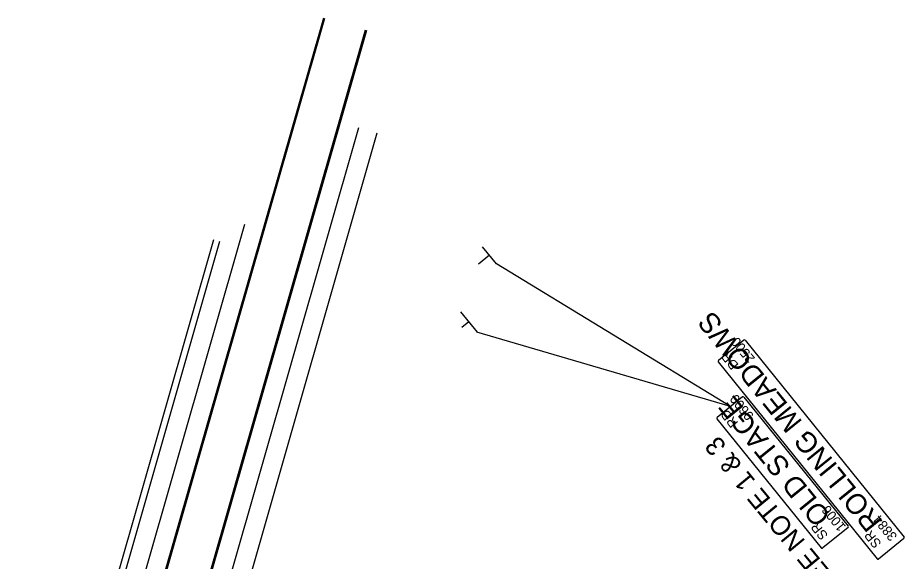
# Model space of a CAD drawing. Extents: x 2096670 to 2098561, y 684033 to 689893.
# Drawn here: x 2097899 to 2098454, y 689553 to 689893 of the extents above; entities that cross this region are included whole.
import ezdxf

# ---------------------------------------------------------------- set-up
doc = ezdxf.new("R2010")
doc.units = 0
for name, color, linetype in [('Exist CMT EOP', 7, 'Continuous'), ('Exist Sign D', 7, 'Continuous'), ('Exist Sign E Stop CELL', 7, 'Continuous'), ('Exist Support 1', 7, 'Continuous'), ('Prop DSN Text', 7, 'Continuous')]:
    doc.layers.add(name, color=color, linetype=linetype)

msp = doc.modelspace()

# ---------------------------------------------------------------- linework, layer by layer
at = {"layer": 'Exist CMT EOP'}
for p, q in [((2097941.37, 689372.39), (2098090.53, 689893.46)), ((2097942.09, 689372.19), (2098091.25, 689893.26)), ((2097967.57, 689364.89), (2098116.73, 689885.97)), ((2097968.29, 689364.69), (2098117.45, 689885.76)), ((2097898.92, 689078.74), (2098112.47, 689824.77)), ((2098006.77, 689411.92), (2098124.01, 689821.47)), ((2097903.97, 689285.33), (2098041.05, 689764.21)), ((2097908.27, 689358.52), (2098021.68, 689754.69)), ((2097916.92, 689374.18), (2098025.53, 689753.59))]:
    msp.add_line(p, q, dxfattribs=at)
at = {"layer": 'Exist Sign D'}
for p, q in [((2098345.15, 689649.95), (2098198.64, 689739.3)), ((2098353.51, 689691.63), (2098337.63, 689678.77)), ((2098354.36, 689691.54), (2098453.85, 689568.23)), ((2098337.54, 689677.91), (2098437.02, 689554.6)), ((2098352.65, 689656.02), (2098336.77, 689643.16)), ((2098353.51, 689655.93), (2098418.86, 689575.16)), ((2098336.68, 689642.31), (2098402.03, 689561.53)), ((2098418.77, 689574.31), (2098402.89, 689561.44)), ((2098453.76, 689567.38), (2098437.88, 689554.51))]:
    msp.add_line(p, q, dxfattribs=at)
for centre, start, end in [((2098353.89, 689691.16), 39.0056, 129.0056), ((2098338.01, 689678.29), 129.0056, 219.0056), ((2098353.03, 689655.55), 39.0056, 129.0056), ((2098337.15, 689642.69), 129.0056, 219.0056), ((2098418.39, 689574.78), 309.0056, 39.0056), ((2098453.37, 689567.85), 309.0056, 39.0056), ((2098402.51, 689561.92), 219.0056, 309.0056), ((2098437.49, 689554.99), 219.0056, 309.0056)]:
    msp.add_arc(centre, 0.609, start, end, dxfattribs=at)
at = {"layer": 'Exist Sign E Stop CELL'}
msp.add_line((2098345.15, 689649.95), (2098186.46, 689696.66), dxfattribs=at)
at = {"layer": 'Exist Support 1'}
for p, q in [((2098176.14, 689709.4), (2098186.49, 689696.61)), ((2098181.36, 689702.96), (2098177.01, 689699.44))]:
    msp.add_line(p, q, dxfattribs=at)
at = {"layer": 'Prop DSN Text'}
for p, q in [((2098198.64, 689739.3), (2098189.98, 689750.01)), ((2098194.28, 689744.7), (2098187.34, 689739.09))]:
    msp.add_line(p, q, dxfattribs=at)

# ---------------------------------------------------------------- texts
at = {"layer": 'Exist Sign D'}
for s, height, p in [('ROLLING MEADOWS', 12.8025, (2098440.9, 689578.26)), ('2500', 6, (2098360.85, 689680.19)), ('DR', 6, (2098350.62, 689676.12)), ('OLD STAGE ', 12.803, (2098408.46, 689581.57)), ('9600', 6, (2098360.14, 689644.4)), ('RD', 6, (2098350.3, 689639.83)), ('1006', 6, (2098417.72, 689574.86)), ('3884', 6, (2098449.9, 689568.88)), ('SR', 6, (2098406.6, 689569.46)), ('SR', 6, (2098440.04, 689564.34))]:
    msp.add_text(s, height=height, rotation=129.0056, dxfattribs=at).set_placement(p)
at = {"layer": 'Prop DSN Text'}
msp.add_text('SEE NOTE 1 & 3', height=12, rotation=129.5118, dxfattribs=at).set_placement((2098415.76, 689537.43))

doc.saveas('drawing.dxf')
